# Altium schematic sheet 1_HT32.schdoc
size 904 x 266 mm
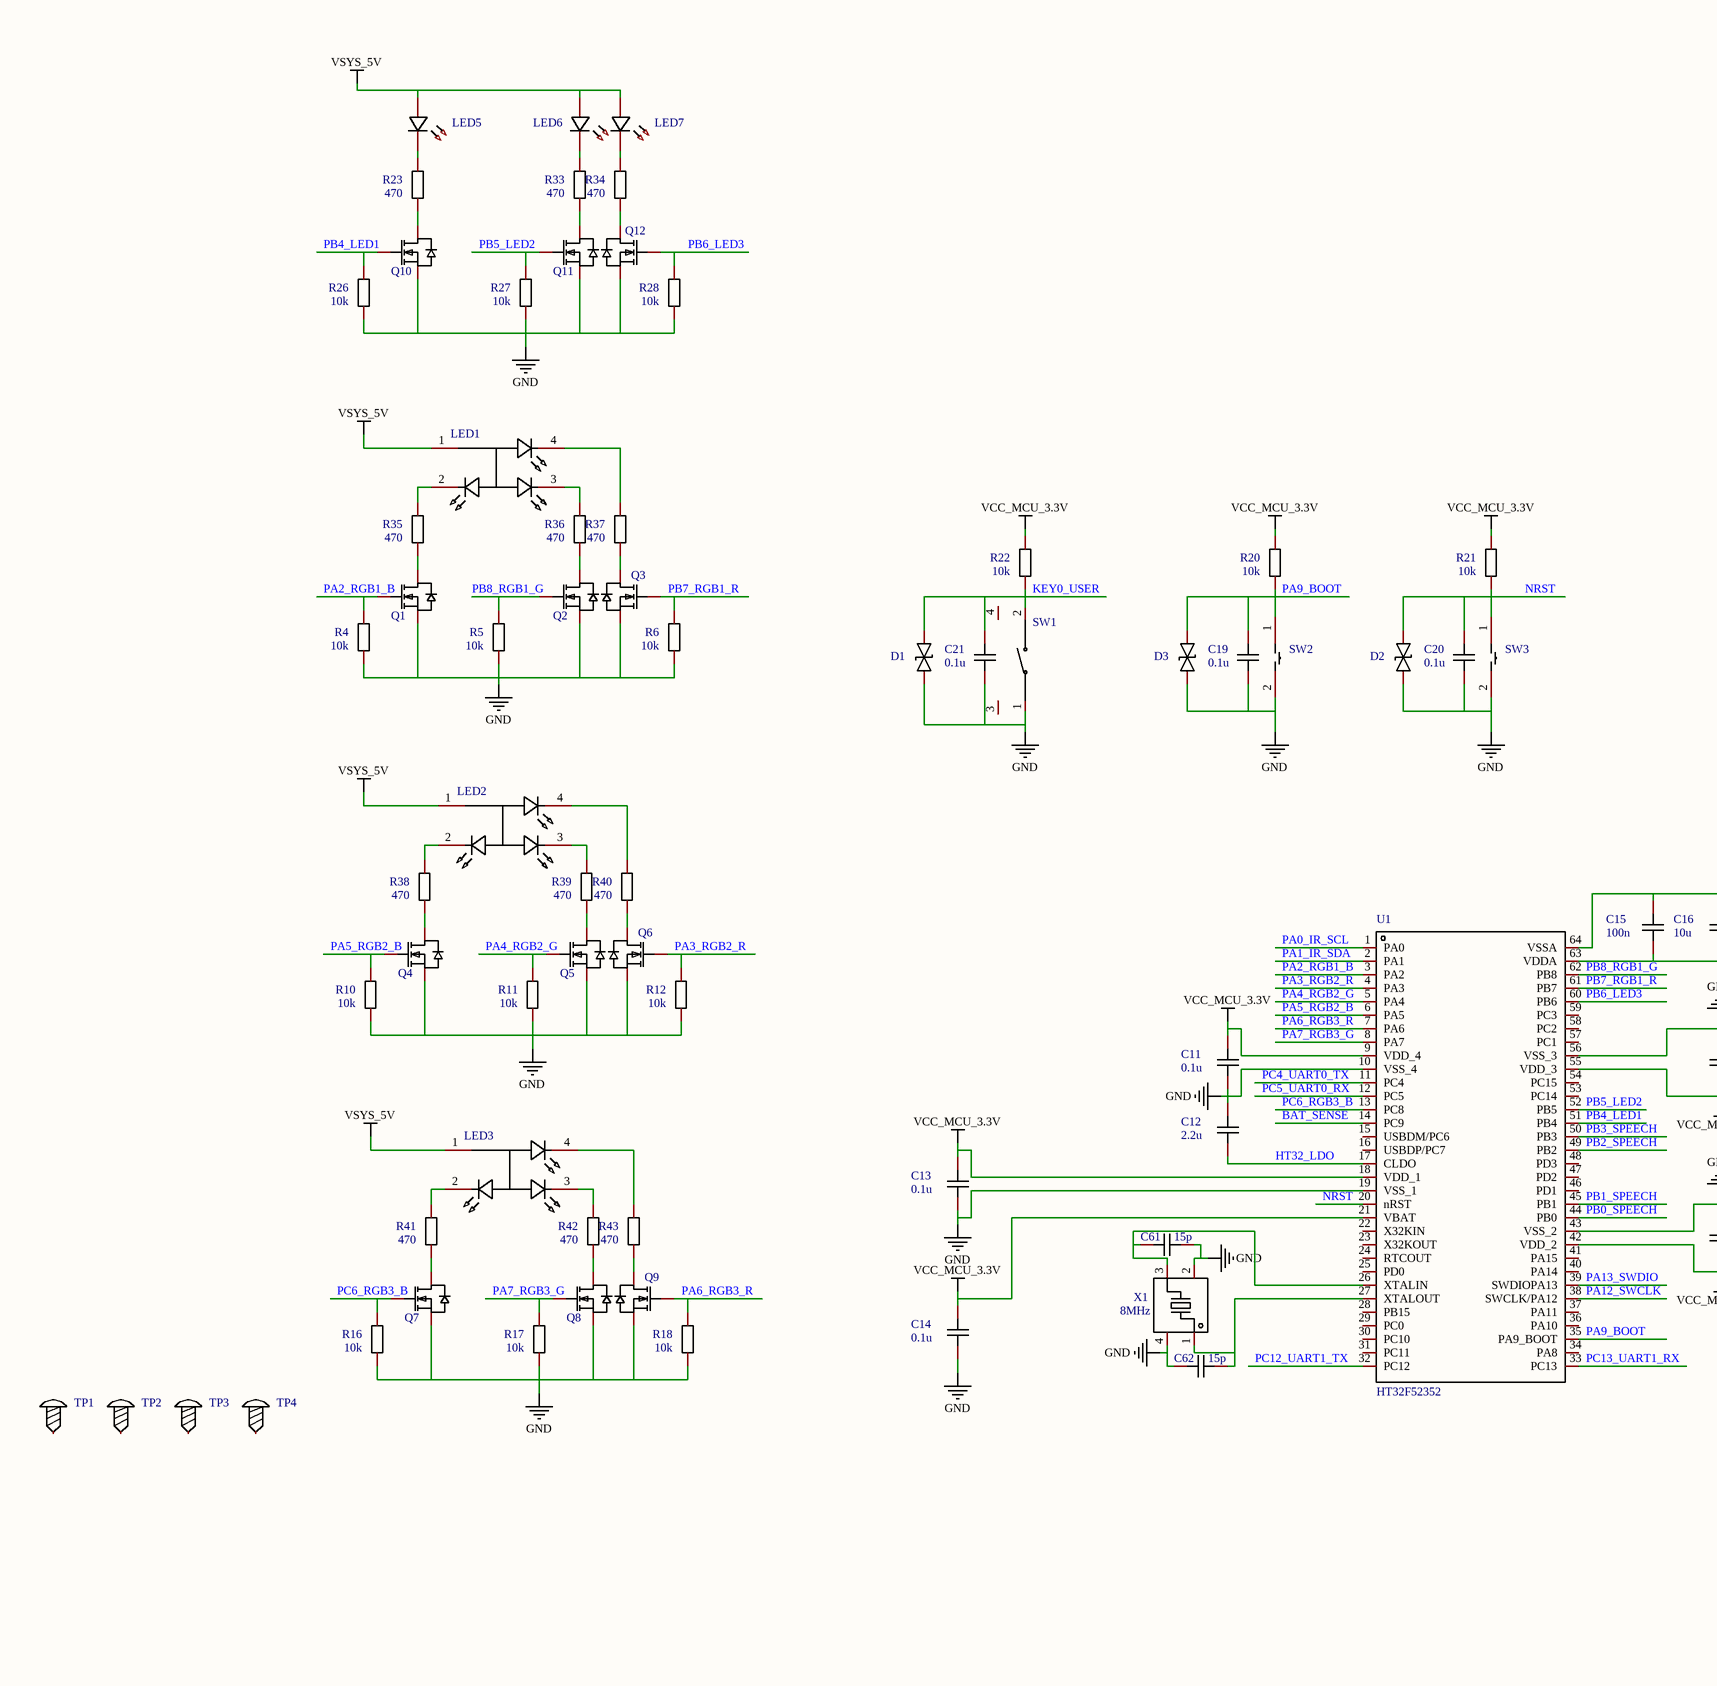
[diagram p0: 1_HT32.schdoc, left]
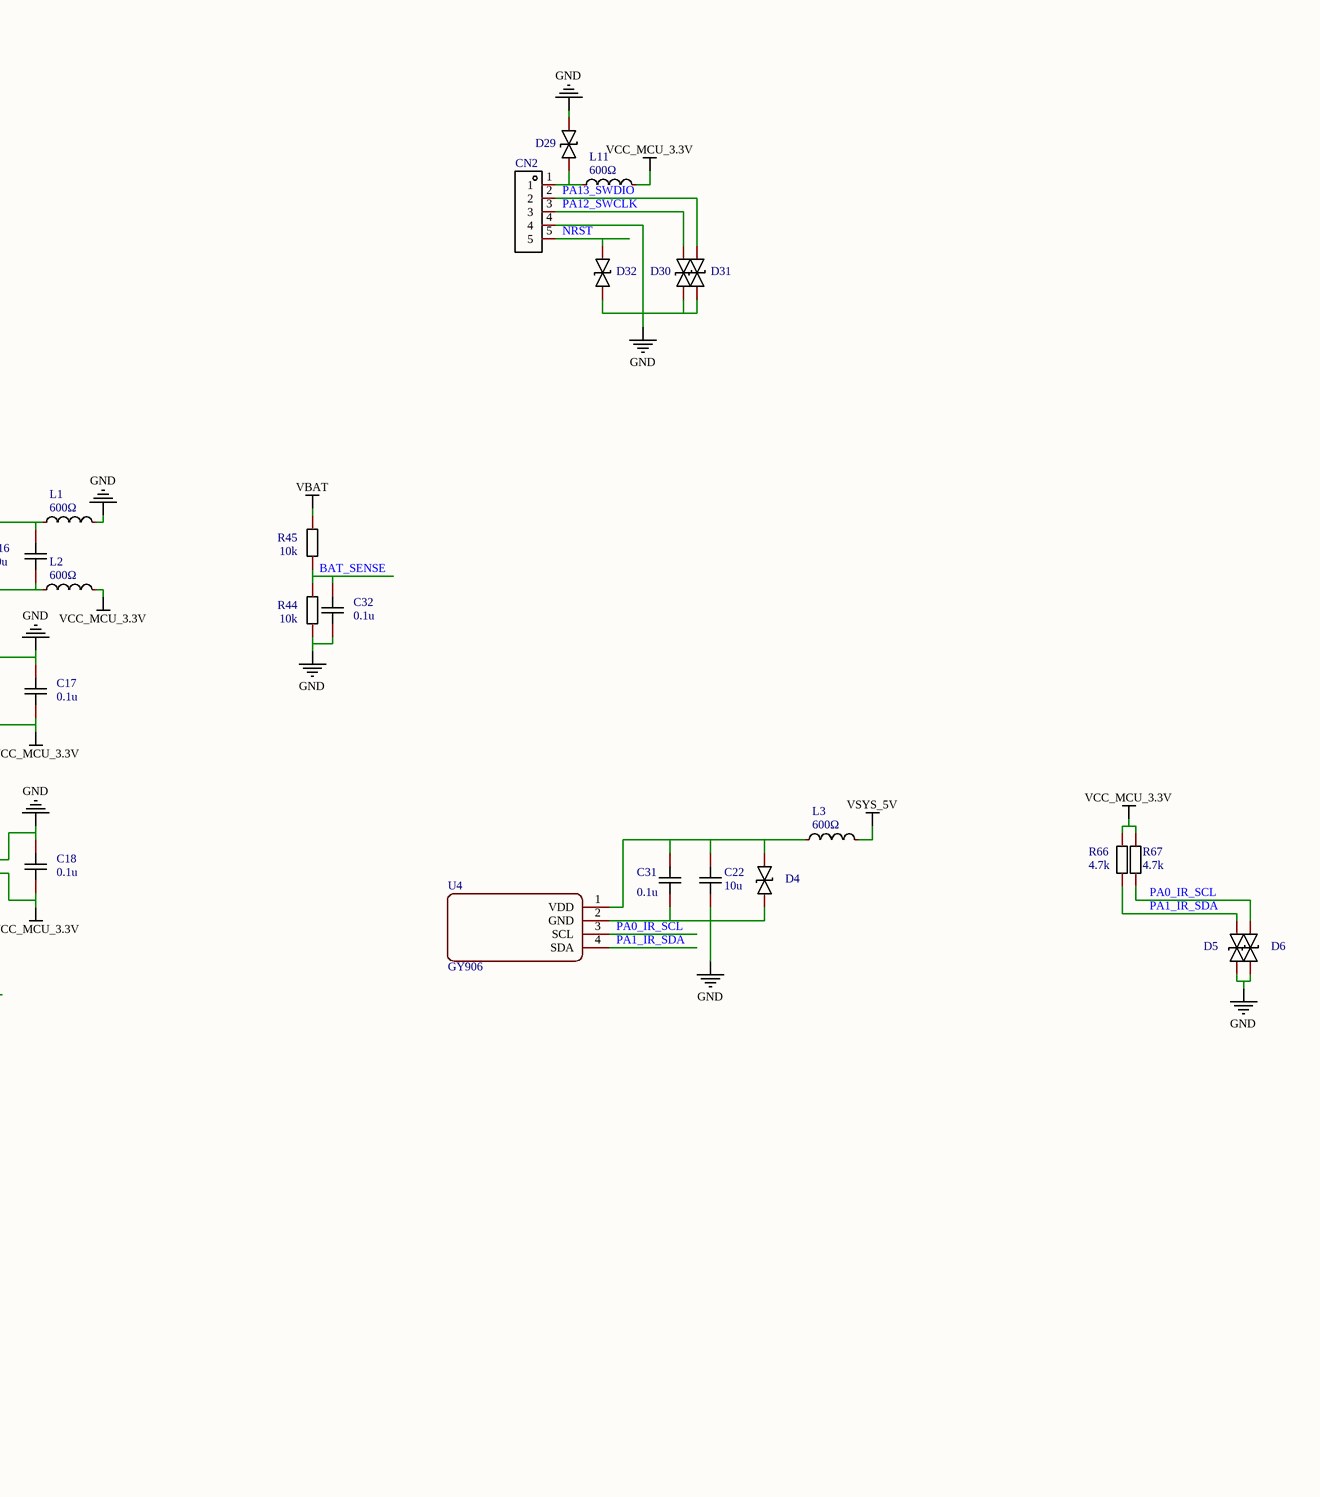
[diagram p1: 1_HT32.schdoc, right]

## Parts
C11  0.1u  [C0603]
C12  2.2u  [C0603]
C13  0.1u  [C0603]
C14  0.1u  [C0603]
C15  100n  [C0603]
C16  10u  [C0603]
C17  0.1u  [C0603]
C18  0.1u  [C0603]
C19  0.1u  [C0603]
C20  0.1u  [C0603]
C21  0.1u  [C0603]
C22  10u  [C0603]
C31  0.1u  [C0603]
C32  0.1u  [C0603]
C61  15p  [C0603]
C62  15p  [C0603]
CN2  XH-5AW  [CONN-TH_5P-P2.54_XH-5AW_C2908614]  (value not drawn)
D1  SD03C  [SOD-323_L1.8-W1.3-LS2.5-BI]  (value not drawn)
D2  SD03C  [SOD-323_L1.8-W1.3-LS2.5-BI]  (value not drawn)
D3  SD03C  [SOD-323_L1.8-W1.3-LS2.5-BI]  (value not drawn)
D4  SD03C  [SOD-323_L1.8-W1.3-LS2.5-BI]  (value not drawn)
D5  SD03C  [SOD-323_L1.8-W1.3-LS2.5-BI]  (value not drawn)
D6  SD03C  [SOD-323_L1.8-W1.3-LS2.5-BI]  (value not drawn)
D29  SD03C  [SOD-323_L1.8-W1.3-LS2.5-BI]  (value not drawn)
D30  SD03C  [SOD-323_L1.8-W1.3-LS2.5-BI]  (value not drawn)
D31  SD03C  [SOD-323_L1.8-W1.3-LS2.5-BI]  (value not drawn)
D32  SD03C  [SOD-323_L1.8-W1.3-LS2.5-BI]  (value not drawn)
L1  600Ω  [L0603]
L2  600Ω  [L0603]
L3  600Ω  [L0603]
L11  600Ω  [L0603]
LED1  XL-3528RGBW-HM  [LED-SMD_4P-L3.2-W2.8-LS3.5-BL-CW]  (value not drawn)
LED2  XL-3528RGBW-HM  [LED-SMD_4P-L3.2-W2.8-LS3.5-BL-CW]  (value not drawn)
LED3  XL-3528RGBW-HM  [LED-SMD_4P-L3.2-W2.8-LS3.5-BL-CW]  (value not drawn)
LED5  LED_0603-G  [LED_0603]  (value not drawn)
LED6  LED_0603-G  [LED_0603]  (value not drawn)
LED7  LED_0603-G  [LED_0603]  (value not drawn)
Q1  2N7002  [SOT-23-3_L2.9-W1.3-P1.90-LS2.4-BR]  (value not drawn)
Q2  2N7002  [SOT-23-3_L2.9-W1.3-P1.90-LS2.4-BR]  (value not drawn)
Q3  2N7002  [SOT-23-3_L2.9-W1.3-P1.90-LS2.4-BR]  (value not drawn)
Q4  2N7002  [SOT-23-3_L2.9-W1.3-P1.90-LS2.4-BR]  (value not drawn)
Q5  2N7002  [SOT-23-3_L2.9-W1.3-P1.90-LS2.4-BR]  (value not drawn)
Q6  2N7002  [SOT-23-3_L2.9-W1.3-P1.90-LS2.4-BR]  (value not drawn)
Q7  2N7002  [SOT-23-3_L2.9-W1.3-P1.90-LS2.4-BR]  (value not drawn)
Q8  2N7002  [SOT-23-3_L2.9-W1.3-P1.90-LS2.4-BR]  (value not drawn)
Q9  2N7002  [SOT-23-3_L2.9-W1.3-P1.90-LS2.4-BR]  (value not drawn)
Q10  2N7002  [SOT-23-3_L2.9-W1.3-P1.90-LS2.4-BR]  (value not drawn)
Q11  2N7002  [SOT-23-3_L2.9-W1.3-P1.90-LS2.4-BR]  (value not drawn)
Q12  2N7002  [SOT-23-3_L2.9-W1.3-P1.90-LS2.4-BR]  (value not drawn)
R4  10k  [R0603]
R5  10k  [R0603]
R6  10k  [R0603]
R10  10k  [R0603]
R11  10k  [R0603]
R12  10k  [R0603]
R16  10k  [R0603]
R17  10k  [R0603]
R18  10k  [R0603]
R20  10k  [R0603]
R21  10k  [R0603]
R22  10k  [R0603]
R23  470  [R0603]
R26  10k  [R0603]
R27  10k  [R0603]
R28  10k  [R0603]
R33  470  [R0603]
R34  470  [R0603]
R35  470  [R0603]
R36  470  [R0603]
R37  470  [R0603]
R38  470  [R0603]
R39  470  [R0603]
R40  470  [R0603]
R41  470  [R0603]
R42  470  [R0603]
R43  470  [R0603]
R44  10k  [R0603]
R45  10k  [R0603]
R66  4.7k  [R0603]
R67  4.7k  [R0603]
SW1  KAN0637-0701B  [SW-TH_KAN0637-0701B]  (value not drawn)
SW2  YTSA010A0252501B  [SW-SMD_L4.0-W3.0-LS5.0]  (value not drawn)
SW3  YTSA010A0252501B  [SW-SMD_L4.0-W3.0-LS5.0]  (value not drawn)
TP1  M3螺丝  [M3螺丝]  (value not drawn)
TP2  M3螺丝  [M3螺丝]  (value not drawn)
TP3  M3螺丝  [M3螺丝]  (value not drawn)
TP4  M3螺丝  [M3螺丝]  (value not drawn)
U1  HT32F52352  [LQFP-64_L7.0-W7.0-P0.40-LS9.2-BL]
U4  GY906  [GY906]
X1  8MHz  [CRYSTAL-SMD_4P-L3.2-W2.5-BL]

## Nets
GND: C11.1 C12.2 C13.1 C14.1 C17.1 C18.1 C19.1 C20.1 C21.1 C22.1 C31.2 C32.1 C61.2 C62.1 CN2.4 D1.2 D2.2 D3.2 D4.2 D5.2 D6.2 D29.2 D30.2 D31.2 D32.2 L1.2 Q1.2(S) Q2.2(S) Q3.2(S) Q4.2(S) Q5.2(S) Q6.2(S) Q7.2(S) Q8.2(S) Q9.2(S) Q10.2(S) Q11.2(S) Q12.2(S) R4.1 R5.1 R6.1 R10.1 R11.1 R12.1 R16.1 R17.1 R18.1 R26.1 R27.1 R28.1 R44.1 SW1.1 SW2.2 SW3.2 U1.10(VSS_4) U1.19(VSS_1) U1.43(VSS_2) U1.56(VSS_3) U4.2(GND) X1.2(GND) X1.4(GND)
VBAT: R45.2
VCC_MCU_3.3V: C11.2 C13.2 C14.2 C17.2 C18.2 L2.2 L11.2 R20.2 R21.2 R22.2 R66.2 R67.2 U1.9(VDD_4) U1.18(VDD_1) U1.21(VBAT) U1.42(VDD_2) U1.55(VDD_3)
VSYS_5V: L3.2 LED1.1(+) LED2.1(+) LED3.1(+) LED5.2(A) LED6.2(A) LED7.2(A)
BAT_SENSE: C32.2 R44.2 R45.1 U1.14(PC9)
HT32_LDO: C12.1 U1.17(CLDO)
KEY0_USER: C21.2 D1.1 R22.1 SW1.2
NRST: C20.2 CN2.5 D2.1 D32.1 R21.1 SW3.1 U1.20(nRST)
PA0_IR_SCL: D6.1 R67.1 U1.1(PA0) U4.3(SCL)
PA1_IR_SDA: D5.1 R66.1 U1.2(PA1) U4.4(SDA)
PA2_RGB1_B: Q1.1(G) R4.2 U1.3(PA2)
PA3_RGB2_R: Q6.1(G) R12.2 U1.4(PA3)
PA4_RGB2_G: Q5.1(G) R11.2 U1.5(PA4)
PA5_RGB2_B: Q4.1(G) R10.2 U1.6(PA5)
PA6_RGB3_R: Q9.1(G) R18.2 U1.7(PA6)
PA7_RGB3_G: Q8.1(G) R17.2 U1.8(PA7)
PA9_BOOT: C19.2 D3.1 R20.1 SW2.1 U1.35(PA9_BOOT)
PA12_SWCLK: CN2.3 D30.1 U1.38(SWCLK/PA12)
PA13_SWDIO: CN2.2 D31.1 U1.39(SWDIOPA13)
PB0_SPEECH: U1.44(PB0)
PB1_SPEECH: U1.45(PB1)
PB2_SPEECH: U1.49(PB2)
PB3_SPEECH: U1.50(PB3)
PB4_LED1: Q10.1(G) R26.2 U1.51(PB4)
PB5_LED2: Q11.1(G) R27.2 U1.52(PB5)
PB6_LED3: Q12.1(G) R28.2 U1.60(PB6)
PB7_RGB1_R: Q3.1(G) R6.2 U1.61(PB7)
PB8_RGB1_G: Q2.1(G) R5.2 U1.62(PB8)
PC4_UART0_TX: U1.11(PC4)
PC5_UART0_RX: U1.12(PC5)
PC6_RGB3_B: Q7.1(G) R16.2 U1.13(PC8)
PC12_UART1_TX: U1.32(PC12)
PC13_UART1_RX: U1.33(PC13)
NetC15_1: C15.1 C16.1 L2.1 U1.63(VDDA)
NetC15_2: C15.2 C16.2 L1.1 U1.64(VSSA)
NetC22_2: C22.2 C31.1 D4.1 L3.1 U4.1(VDD)
NetC61_1: C61.1 U1.26(XTALIN) X1.3
NetC62_2: C62.2 U1.27(XTALOUT) X1.1
NetCN2_1: CN2.1 D29.1 L11.1
NetLED1_2: LED1.2(B-) R35.2
NetLED1_3: LED1.3(G-) R36.2
NetLED1_4: LED1.4(R-) R37.2
NetLED2_2: LED2.2(B-) R38.2
NetLED2_3: LED2.3(G-) R39.2
NetLED2_4: LED2.4(R-) R40.2
NetLED3_2: LED3.2(B-) R41.2
NetLED3_3: LED3.3(G-) R42.2
NetLED3_4: LED3.4(R-) R43.2
NetLED5_1: LED5.1(C) R23.2
NetLED6_1: LED6.1(C) R33.2
NetLED7_1: LED7.1(C) R34.2
NetQ1_3: Q1.3(D) R35.1
NetQ2_3: Q2.3(D) R36.1
NetQ3_3: Q3.3(D) R37.1
NetQ4_3: Q4.3(D) R38.1
NetQ5_3: Q5.3(D) R39.1
NetQ6_3: Q6.3(D) R40.1
NetQ7_3: Q7.3(D) R41.1
NetQ8_3: Q8.3(D) R42.1
NetQ9_3: Q9.3(D) R43.1
NetQ10_3: Q10.3(D) R23.1
NetQ11_3: Q11.3(D) R33.1
NetQ12_3: Q12.3(D) R34.1

Not connected (* = marked no-connect by the designer): SW1 3 4; TP1 1; TP2 1; TP3 1; TP4 1; U1 15(USBDM/PC6) 16(USBDP/PC7) 22(X32KIN) 23(X32KOUT) 24(RTCOUT) 25(PD0) 28(PB15) 29(PC0) 30(PC10) 31(PC11) 34(PA8) 36(PA10) 37(PA11) 40(PA14) 41(PA15) 46(PD1) 47(PD2) 48(PD3) 53(PC14) 54(PC15) 57(PC1) 58(PC2) 59(PC3)

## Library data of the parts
C11-C22 C31 C32 C61 C62 = CAP_0603: Symbol: CapAcitance; Convert to PCB: yes
CN2 = XH-5AW: 参考系列:XH;间距:2.54mm;插针结构:1x5P;排数:1;每排PIN数:5;行距:-;公母:公型插针;安装方式:弯插;额定电流:3A;工作温度范围:-25℃~+85℃;; Manufacturer: HCTL(华灿天禄); Symbol: XH-5AW_C2908614; Add into BOM: yes; Reference Series: XH; Pitch: 2.54mm; Pins Structure: 1x5P; Number of PINs Per Row: 5; Gender: 公型插针; Current Rating (Max): 3A
D1-D6 D29-D32 = SD03C_C502532: 极性:双向;反向截止电压(Vrwm):3.3V;击穿电压(最小值):4V;峰值脉冲电流(Ipp)@10/1000μs:20A;最大钳位电压:16V;; Manufacturer: MDD; Add into BOM: yes; Polarity: 双向; Reverse Stand-Off Voltage (Vrwm): 3.3V; Breakdown Voltage (Min): 4V; Peak Pulse Current (Ipp)@10/1000μs: 20A; Maximum Clamping Voltage: 16V
L1-L3 L11 = L_0603: Symbol: SDFL1608S100KTF; Add into BOM: yes
LED1-LED3 = XL-3528RGBW-HM: 3528七彩黑面贴片LED灯珠 3528 七彩黑面(IV:R:171-240/G:650-845/B:110-143mcd(Typ)@IF=20mA); Manufacturer: XINGLIGHT(成兴光); Add into BOM: yes
LED5-LED7 = LED_0603-G: Symbol: LED_G; Convert to PCB: yes
Q1-Q12 = 2N7002: 类型:N沟道;漏源电压(Vdss):60V;连续漏极电流(Id):115mA;功率(Pd):200mW;导通电阻(RDS(on)@Vgs,Id):7.5Ω@10V,500mA;阈值电压(Vgs(th)@Id):2.5V@250A;; Manufacturer: CJ（江苏长电/长晶）; Add into BOM: yes; Type: N沟道; Drain Source Voltage (Vdss): 60V; Continuous Drain Current (Id): 115mA; Power Dissipation (Pd): 200mW
R4-R6 R10-R12 R16-R18 R20-R22 R26-R28 R44 R45 = AECR0603F1K50K9: Manufacturer: RESI(开步睿思）; Add into BOM: yes; Tolerance: ±1%; Power(Watts): 100mW; Temperature Coefficient: ±100ppm/℃; Overload Voltage (Max): 50V; Description: 电阻类型:厚膜电阻;阻值:1.5kΩ;精度:±1%;功率:100mW;温度系数:±100ppm/℃;最大工作电压:50V;工作温度范围:-55℃~+125℃;
R23 R33-R43 = AECR0603F1K50K9: Manufacturer: RESI(开步睿思）; Add into BOM: yes; Value: 200; Tolerance: ±1%; Power(Watts): 100mW; Temperature Coefficient: ±100ppm/℃; Overload Voltage (Max): 50V; Description: 电阻类型:厚膜电阻;阻值:1.5kΩ;精度:±1%;功率:100mW;温度系数:±100ppm/℃;最大工作电压:50V;工作温度范围:-55℃~+125℃;
R66 R67 = Res_0603: Symbol: 电阻; Convert to PCB: yes
SW1 = KAN0637-0701B: 触点电流:50mA;额定电压(DC):12V;电路结构:单刀单掷;按钮作用方向:侧面触动;致动器样式:圆形按钮;照明颜色:-;; Manufacturer: GANGYUAN(港源); Add into BOM: yes; Contact Current: 50mA; Voltage Rating (DC): 12V; Circuit: 单刀单掷; Actuator Orientation: 侧面触动; Actuator Style: 圆形按钮
SW2 SW3 = YTSA010A0252501B: 触点电流:50mA;额定电压(DC):12V;绝缘电阻:100MΩ;电路结构:单刀单掷;安装方式:立贴;按钮形状:圆形按钮;按钮/盖帽颜色:黑色;作用力:250gf;机械寿命:50000;引脚样式:SMD接片;开关长度:4mm;开关宽度:3mm;开关高度:2.5mm;带支架:否;; Manufacturer: DGBZ(东莞博众); Add into BOM: yes; Contact Current: 50mA; Voltage Rating (DC): 12V; Insulation Resistance: 100MΩ; Circuit: 单刀单掷; Actuator Style: 圆形按钮; Actuator/Cap Color: 黑色; Operating Force: 250gf; Mechanical Life: 50000; Pin Style: SMD接片; Switch Length: 4mm; Switch Width: 3mm; Switch Height: 2.5mm; Strike Gundam: 否
TP1-TP4 = M3螺丝: Symbol: 螺丝孔; Convert to PCB: yes
U1 = HT32F52352: CPU内核:ARM Cortex-M0;CPU最大主频:48MHz;程序存储容量:128KB;程序存储器类型:FLASH;RAM总容量:16KB;GPIO端口数量:51;; Manufacturer: HOLTEK(合泰/盛群); Add into BOM: yes; CPU Maximum Speed: 48MHz; Operating Voltage Range: 2V~3.6V; Program Storage Size: 128KB; Program Memory Type: FLASH; RAM Size: 16KB; GPIO Ports Number: 51; ADC (Bit): 12bit; 16Bit Timer: 5; 32Bit Timer: 2; UART/USART: 4; I2S: 1; Universal Serial Bus: 有; Peripheral/Function: 低电压检测；看门狗；CCP捕获/比较；乘法器；IrDA；CRC校验；DMA；RTC实时时钟
U4 = GY906: Add into BOM: yes; _: 3
X1 = X32258MSB4SI: 频率:8MHz;频率公差:±10ppm;频率稳定度:±30ppm;负载电容:20pF;; Manufacturer: YXC(扬兴晶振); Add into BOM: yes; Crystal Type: 贴片无源晶振; Frequency Tolerance: ±10ppm; Frequency Stability: ±30ppm; Load Capacitance: 20pF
